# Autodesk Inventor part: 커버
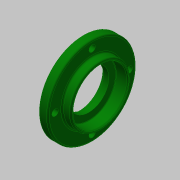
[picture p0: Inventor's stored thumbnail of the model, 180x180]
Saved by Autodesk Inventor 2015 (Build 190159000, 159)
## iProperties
Created: 2018-11
Part Number: 커버
Material: 알루미늄 6061
Document SubType Name: Modeling
Designer: mduedu
Density: 1 g/cm^3
Appearance: 진녹색
Author: mduedu
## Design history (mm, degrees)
sketch "스케치1"
  geometry: L1 (0, 0)-(3, 0); L2 (3, 0)-(3, 20); L3 (3, 20)-(0, 20); L4 (0, 20)-(0, 0); L5 (3, 0)-(9, 0); L6 (9, 0)-(9, 31); L7 (9, 31)-(3, 31); L8 (3, 31)-(3, 0); L9 (9, 0)-(15, 0); L10 (15, 0)-(15, 21); L11 (15, 21)-(9, 21); L12 (9, 21)-(9, 0)
  constraints: 24 end point, 6 parallel, 3 horizontal, 3 perpendicular
  dimensions: "d0" = 62 diameter of L7 L5; "d2" = 42 diameter of L11 L9; "d3" = 40 diameter of L3 L1; "d4" = 3 distance of L2.end L3.end; "d5" = 6 distance of L6.end L7.end; "d6" = 15 distance between parallel lines of L10 L4
revolve "회전1" sketch "스케치1" stored, may be unused: angle "d7" = 90 deg
sketch "스케치2"
  geometry: L1 (0, -20)-(0, 20) reference; L2 (0, 20)-(3, 20) reference; L3 (3, 20)-(3, 31) reference; L4 (3, 31)-(9, 31) reference; L5 (9, 31)-(9, 21) reference; L6 (9, 21)-(15, 21) reference; L7 (15, 21)-(15, -21) reference; L8 (15, -21)-(9, -21) reference; L9 (9, -21)-(9, -31) reference; L10 (9, -31)-(3, -31) reference; L11 (3, -31)-(3, -20) reference; L12 (3, -20)-(0, -20) reference; L13 (0, 0)-(3, 0); L14 (3, 0)-(3, 16.5); L15 (3, 16.5)-(0, 16.5); L16 (0, 16.5)-(0, 0); L17 (3, 0)-(6.7, 0); L18 (6.7, 0)-(6.7, 14); L19 (6.7, 14)-(3, 14); L20 (3, 14)-(3, 0); L21 (6.7, 0)-(15, 0); L22 (15, 0)-(15, 19); L23 (15, 19)-(6.7, 19); L24 (6.7, 19)-(6.7, 0)
  constraints: 24 end point, 6 parallel, 3 horizontal, 3 perpendicular, 1 point on line
  dimensions: "d8" = 38 diameter of L23 L21; "d10" = 28 diameter of L19 L17; "d11" = 33 diameter of L15 L13; "d12" = 3 distance of L14.end L15.end; "d13" = 8.3 distance of L22.end L23.end
revolve "회전2" sketch "스케치2" stored, may be unused: angle "d14" = 90 deg
fillet "모깎기1" dims "d15" = 0.3
chamfer "모따기1" distance "d16" = 0.8; stored, may be unused: second distance "d17" = 2, angle "d18" = 30 deg
fillet "모깎기2" dims "d19" = 1
chamfer "모따기2" distance "d20" = 0.5; stored, may be unused: second distance "d21" = 2, angle "d22" = 30 deg
sketch "스케치3" dims "d23" = 52
  geometry: 6 further points
  constraints: 2 vertical alignment, 1 coincident, 7 other
  dimensions: "d26" = 360 deg dimension on point (0, 0) point (0, 26) (derived)
sketch "스케치4"
  geometry: 4 further points
  constraints: 4 other
hole "구멍1" sketch "스케치4" at (-26, 0), (0, -26), (26, 0), (0, 26) diameter "d28" = 4.5; stored, may be unused: countersink angle "d32" = 90 deg, drill point angle "d34" = 0 deg; dims "d29" = 6, "d30" = 8, "d31" = 4.6, "d33" = 8
node "솔리드1"
node "절단 모서리 투영1"
